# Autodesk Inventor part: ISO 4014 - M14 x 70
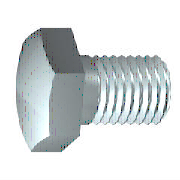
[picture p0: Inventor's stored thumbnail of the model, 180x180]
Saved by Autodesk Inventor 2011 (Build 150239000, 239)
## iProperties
IsCustomPart: 0
Created: 2009-02
Part Number: ISO 4014 - M14 x 70
Material: Stainless Steel, 440C
Description: Hexagon head bolt - product grades A and B
Document SubType Name: Modeling
Standard: ISO 4014
Designer: 904Chiaki
Standard Revision: Third edition 1999-09-01
Standards Organization: ISO
Language: en-US
Size Designation: M14 x 70
Categories: <MemberInstance><Categories><Category DisplayName="Fasteners" InternalName="e4da775c-781d-43d5-af7c-5136215cf5a6" Mnemonic="FSTN"><Category DisplayName="Bolts"
Density: 7.75 g/cm^3
Mass: 108.833 g
Surface Area: 44.2416 cm^2
Volume: 14.043 cm^3
Author: 904Chiaki
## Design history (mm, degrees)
body "Solid1"
workplane "Work Plane1"
revolve "Body" stored, may be unused: angle "d12" = 90 deg
sketch "Sketch2"
  geometry: L1 (0, 12.124)-(10.5, 6.062); L2 (10.5, 6.062)-(10.5, -6.062); L3 (10.5, -6.062)-(0, -12.124); L4 (0, -12.124)-(-10.5, -6.062); L5 (-10.5, -6.062)-(-10.5, 6.062); L6 (-10.5, 6.062)-(0, 12.124); 2 further points
  constraints: 12 end point, 1 coincident, 1 vertical, 11 other
  dimensions: "d11" = 21 distance between parallel lines of L5 L2 (= SW)
extrude "Head" join sketch "Sketch2" distance "d3" = 8.2 (= KOH - SD); taper "d4" = 0 deg
revolve "Chamfer1" stored, may be unused: angle "d21" = 90 deg
feature "Thread" dims "d15" = 34 (= GEL), "d16" = 0
chamfer "Chamfer2" distance "d6" = 1.2269 (= -0.5 x SPD + 0.5 x GD); stored, may be unused: second distance "d7" = 1.227 (computed from GUL), angle "d55" = 45 deg
sketch "Sketch1"
  geometry: L1 (0, 9.685)-(0, 7); L2 (36, 7)-(70, 7); L3 (70, 7)-(70, 0); L4 (70, 0)-(-0.6, 0); L5 (-14.72, 0)-(84.12, 0) reference; L6 (-0.6, 0)-(-0.6, 9.685); L7 (-0.6, 9.685)-(0, 9.685); L8 (36, 7)-(34.773, 7); L9 (34.773, 7)-(0, 7); L10 (0, -1.937)-(0, 11.622) reference
  constraints: 16 end point, 2 collinear, 2 perpendicular, 1 parallel
  dimensions: "d0" = 70 distance between parallel lines of L3 L1 (= NLG); "d1" = 34 distance from line of L2.start L3 (= GEL); "d2" = 14 diameter of L2 L4 (= GD); "d9" = 0.6001 distance between parallel lines of L6 L1 (computed from SD); "d10" = 19.37 diameter of L7 L4 (= SD2); "d13" = 1.227 distance of L2.start L8.end (computed from GAL); "d14" = 14 diameter of L9 L4 (= BDM)
sketch "Sketch4"
  geometry: L1 (-8.8, 10.5)-(-8.8, 12.124); L2 (-8.8, 12.124)-(-7.862, 12.124); L3 (-7.862, 12.124)-(-8.8, 10.5); L4 (-10.44, 0)-(1.04, 0) reference; L5 (-0.6, 12.124)-(-8.8, 12.124) reference; L6 (-8.8, 6.062)-(-8.8, 12.124) reference
  constraints: 6 end point, 2 collinear, 1 perpendicular, 1 vertical
  dimensions: "d5" = 30 deg angle of L3 L1 (= ANG1); "d19" = 21 diameter of L1.start L4 (= SW0)
other parameters: "NLG" = 70 [user parameter; used in 1 equation term], "GD" = 14 (= NND) [user parameter; used in 2 equation terms], "BDM" = 14 (= NND) [user parameter; used in 1 equation term], "KOH" = 8.8 [user parameter; used in 1 equation term], "GEL" = 34 [user parameter; used in 2 equation terms], "SW" = 21 [user parameter; used in 3 equation terms], "SW0" = 21 (= SW) [user parameter; used in 1 equation term], "SPD" = 11.5462 (= NND - 1.2269 x PTC) [user parameter; used in 1 equation term], "SD2" = 19.37 [user parameter; used in 2 equation terms], "SD" = 0.6 [user parameter; used in 2 equation terms], "ANG1" = 30 deg [user parameter; used in 1 equation term], "GAL" = 1.2269 (= 0.61345 x PTC) [user parameter; used in 1 equation term], "GUL" = 1.2269 (= 0.61345 x PTC) [user parameter; used in 1 equation term], "d8" = 0, "RR" = 0.6 [user parameter], "d57" = 0, "d58" = 0, "TPU" = 5 (computed from PTC) [user parameter], "GD1" = 11.5462 (= THREADDIA - 1.2269 x PTC) [user parameter], "THREADDIA" = 14 [user parameter; used in 1 equation term], "SDH" = 19.37 (= SD2) [user parameter], "TOA" = 30 deg [user parameter], "PTC" = 2 [user parameter; used in 5 equation terms], "NND" = 14 [user parameter; used in 3 equation terms], "E0" = 24.255 (= 1.155 x SW) [user parameter]
